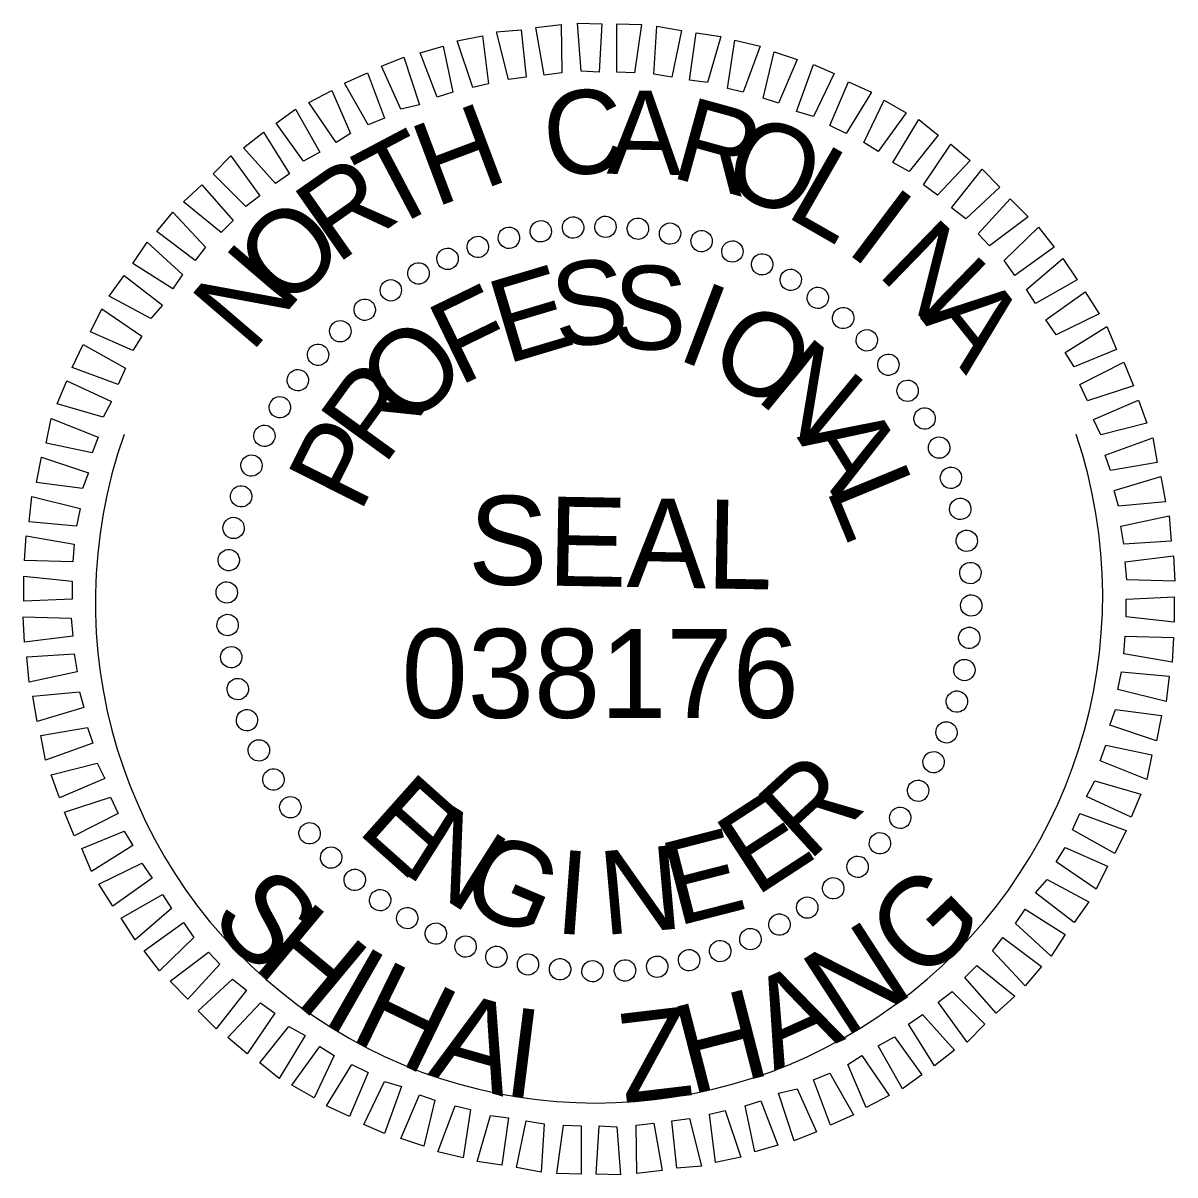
# Model space of a CAD drawing. Extents: x 885343.6 to 885383.5, y 651350.8 to 651372.8.
# Drawn here: x 885378.006 to 885379.558, y 651369.841 to 651371.393 of the extents above; entities that cross this region are included whole.
import ezdxf

# ---------------------------------------------------------------- set-up
doc = ezdxf.new("R2010")
doc.units = 0
doc.layers.add('Sheet PE Seal Cell', color=7, linetype='Continuous')
doc.layers.add('Sheet Plot Border Outside CELL', color=7, linetype='Continuous')

msp = doc.modelspace()

# ---------------------------------------------------------------- linework, layer by layer
at = {"layer": 'Sheet PE Seal Cell'}
for p, q in [((885378.7041, 651371.1119), (885378.7041, 651371.1119)), ((885378.7471, 651371.1179), (885378.7471, 651371.1179)), ((885378.7911, 651371.1189), (885378.7911, 651371.1189)), ((885378.8351, 651371.1159), (885378.8351, 651371.1159)), ((885378.6601, 651371.1039), (885378.6601, 651371.1039)), ((885378.8781, 651371.1089), (885378.8781, 651371.1089)), ((885378.9201, 651371.0999), (885378.9201, 651371.0999)), ((885378.6181, 651371.0919), (885378.6181, 651371.0919)), ((885378.9621, 651371.0859), (885378.9621, 651371.0859)), ((885378.5781, 651371.0759), (885378.5781, 651371.0759)), ((885379.0021, 651371.0679), (885379.0021, 651371.0679)), ((885378.5391, 651371.0559), (885378.5391, 651371.0559)), ((885379.0411, 651371.0479), (885379.0411, 651371.0479)), ((885378.5011, 651371.0329), (885378.5011, 651371.0329)), ((885379.0771, 651371.0229), (885379.0771, 651371.0229)), ((885378.4661, 651371.0079), (885378.4661, 651371.0079)), ((885379.1121, 651370.9959), (885379.1121, 651370.9959)), ((885378.4331, 651370.9779), (885378.4331, 651370.9779)), ((885379.1431, 651370.9659), (885379.1431, 651370.9659)), ((885378.4031, 651370.9469), (885378.4031, 651370.9469)), ((885379.1731, 651370.9329), (885379.1731, 651370.9329)), ((885378.3761, 651370.9119), (885378.3761, 651370.9119)), ((885379.1981, 651370.8979), (885379.1981, 651370.8979)), ((885378.3511, 651370.8759), (885378.3511, 651370.8759)), ((885379.2211, 651370.8599), (885379.2211, 651370.8599)), ((885378.3311, 651370.8369), (885378.3311, 651370.8369)), ((885379.2411, 651370.8209), (885379.2411, 651370.8209)), ((885378.3131, 651370.7969), (885378.3131, 651370.7969)), ((885379.2571, 651370.7809), (885379.2571, 651370.7809)), ((885378.2991, 651370.7549), (885378.2991, 651370.7549)), ((885379.2691, 651370.7389), (885379.2691, 651370.7389)), ((885378.2901, 651370.7129), (885378.2901, 651370.7129)), ((885379.2771, 651370.6949), (885379.2771, 651370.6949)), ((885378.2831, 651370.6699), (885378.2831, 651370.6699)), ((885379.2831, 651370.6519), (885379.2831, 651370.6519)), ((885378.2801, 651370.6259), (885378.2801, 651370.6259)), ((885379.2841, 651370.6079), (885379.2841, 651370.6079)), ((885378.2811, 651370.5819), (885378.2811, 651370.5819)), ((885379.2811, 651370.5639), (885379.2811, 651370.5639)), ((885378.2871, 651370.5389), (885378.2871, 651370.5389)), ((885379.2741, 651370.5209), (885379.2741, 651370.5209)), ((885378.2951, 651370.4949), (885378.2951, 651370.4949)), ((885379.2651, 651370.4789), (885379.2651, 651370.4789)), ((885378.3071, 651370.4529), (885378.3071, 651370.4529)), ((885379.2511, 651370.4369), (885379.2511, 651370.4369)), ((885378.3231, 651370.4129), (885378.3231, 651370.4129)), ((885379.2331, 651370.3969), (885379.2331, 651370.3969)), ((885378.3431, 651370.3739), (885378.3431, 651370.3739)), ((885379.2131, 651370.3579), (885379.2131, 651370.3579)), ((885378.3661, 651370.3359), (885378.3661, 651370.3359)), ((885379.1881, 651370.3219), (885379.1881, 651370.3219)), ((885378.3911, 651370.3009), (885378.3911, 651370.3009)), ((885379.1611, 651370.2869), (885379.1611, 651370.2869)), ((885378.4211, 651370.2679), (885378.4211, 651370.2679)), ((885379.1311, 651370.2559), (885379.1311, 651370.2559)), ((885378.4521, 651370.2379), (885378.4521, 651370.2379)), ((885379.0981, 651370.2259), (885379.0981, 651370.2259)), ((885378.4871, 651370.2109), (885378.4871, 651370.2109)), ((885379.0631, 651370.2009), (885379.0631, 651370.2009)), ((885378.5231, 651370.1859), (885378.5231, 651370.1859)), ((885379.0251, 651370.1779), (885379.0251, 651370.1779)), ((885378.5621, 651370.1659), (885378.5621, 651370.1659)), ((885378.6021, 651370.1479), (885378.6021, 651370.1479)), ((885378.9861, 651370.1579), (885378.9861, 651370.1579)), ((885378.6441, 651370.1339), (885378.6441, 651370.1339)), ((885378.9461, 651370.1419), (885378.9461, 651370.1419)), ((885378.6861, 651370.1249), (885378.6861, 651370.1249)), ((885378.7291, 651370.1179), (885378.7291, 651370.1179)), ((885378.8171, 651370.1159), (885378.8171, 651370.1159)), ((885378.8601, 651370.1219), (885378.8601, 651370.1219)), ((885378.9041, 651370.1299), (885378.9041, 651370.1299)), ((885378.7731, 651370.1149), (885378.7731, 651370.1149))]:
    msp.add_line(p, q, dxfattribs=at)
for points in [[(885378.7081, 651371.3229), (885378.6971, 651371.3869), (885378.7311, 651371.3909), (885378.7321, 651371.3259)], [(885378.7581, 651371.3279), (885378.7531, 651371.3929), (885378.7861, 651371.3919), (885378.7821, 651371.3269)], [(885378.8061, 651371.3269), (885378.8061, 651371.3919), (885378.8391, 651371.3909), (885378.8301, 651371.3259)], [(885378.8561, 651371.3239), (885378.8601, 651371.3889), (885378.8931, 651371.3829), (885378.8801, 651371.3199)], [(885378.6121, 651371.3059), (885378.5911, 651371.3689), (885378.6251, 651371.3759), (885378.6331, 651371.3109)], [(885378.6601, 651371.3169), (885378.6441, 651371.3809), (885378.6771, 651371.3839), (885378.6841, 651371.3199)], [(885378.9041, 651371.3159), (885378.9131, 651371.3799), (885378.9461, 651371.3749), (885378.9281, 651371.3129)], [(885378.5641, 651371.2929), (885378.5411, 651371.3529), (885378.5721, 651371.3619), (885378.5851, 651371.2999)], [(885378.9551, 651371.3049), (885378.9651, 651371.3699), (885378.9991, 651371.3619), (885378.9761, 651371.2999)], [(885378.5151, 651371.2769), (885378.4891, 651371.3349), (885378.5191, 651371.3469), (885378.5401, 651371.2829)], [(885379.0031, 651371.2919), (885379.0181, 651371.3539), (885379.0491, 651371.3439), (885379.0241, 651371.2849)], [(885379.0481, 651371.2739), (885379.0711, 651371.3369), (885379.0991, 651371.3249), (885379.0711, 651371.2669)], [(885378.4711, 651371.2559), (885378.4391, 651371.3119), (885378.4701, 651371.3259), (885378.4931, 651371.2649)], [(885379.0931, 651371.2549), (885379.1181, 651371.3139), (885379.1491, 651371.2999), (885379.1151, 651371.2439)], [(885378.4281, 651371.2319), (885378.3911, 651371.2859), (885378.4221, 651371.3019), (885378.4471, 651371.2439)], [(885379.1391, 651371.2319), (885379.1661, 651371.2889), (885379.1961, 651371.2719), (885379.1581, 651371.2199)], [(885378.3841, 651371.2069), (885378.3471, 651371.2579), (885378.3731, 651371.2769), (885378.4061, 651371.2189)], [(885379.1781, 651371.2049), (885379.2131, 651371.2629), (885379.2391, 651371.2419), (885379.2001, 651371.1929)], [(885378.3461, 651371.1769), (885378.3031, 651371.2249), (885378.3301, 651371.2459), (885378.3651, 651371.1899)], [(885379.2191, 651371.1749), (885379.2561, 651371.2299), (885379.2821, 651371.2079), (885379.2381, 651371.1609)], [(885378.3061, 651371.1459), (885378.2621, 651371.1899), (885378.2861, 651371.2139), (885378.3251, 651371.1599)], [(885379.2571, 651371.1439), (885379.2981, 651371.1959), (885379.3221, 651371.1719), (885379.2761, 651371.1289)], [(885378.2731, 651371.1109), (885378.2221, 651371.1519), (885378.2471, 651371.1749), (885378.2891, 651371.1269)], [(885379.2931, 651371.1089), (885379.3361, 651371.1559), (885379.3601, 651371.1319), (885379.3081, 651371.0929)], [(885378.2381, 651371.0729), (885378.1861, 651371.1119), (885378.2081, 651371.1379), (885378.2521, 651371.0909)], [(885379.3281, 651371.0729), (885379.3741, 651371.1179), (885379.3951, 651371.0909), (885379.3421, 651371.0529)], [(885378.2081, 651371.0349), (885378.1541, 651371.0689), (885378.1731, 651371.0979), (885378.2211, 651371.0539)], [(885379.3581, 651371.0339), (885379.4071, 651371.0759), (885379.4261, 651371.0469), (885379.3701, 651371.0149)], [(885378.1781, 651370.9949), (885378.1221, 651371.0249), (885378.1421, 651371.0529), (885378.1941, 651371.0129)], [(885379.3841, 651370.9929), (885379.4371, 651371.0309), (885379.4561, 651371.0009), (885379.3981, 651370.9729)], [(885378.1541, 651370.9519), (885378.0971, 651370.9769), (885378.1121, 651371.0079), (885378.1661, 651370.9709)], [(885379.4101, 651370.9489), (885379.4661, 651370.9839), (885379.4791, 651370.9529), (885379.4221, 651370.9299)], [(885378.1341, 651370.9059), (885378.0721, 651370.9289), (885378.0871, 651370.9599), (885378.1441, 651370.9279)], [(885379.4301, 651370.9059), (885379.4891, 651370.9359), (885379.5021, 651370.9039), (885379.4401, 651370.8839)], [(885378.1141, 651370.8619), (885378.0521, 651370.8799), (885378.0651, 651370.9109), (885378.1251, 651370.8829)], [(885379.4481, 651370.8589), (885379.5091, 651370.8849), (885379.5201, 651370.8539), (885379.4581, 651370.8379)], [(885378.0991, 651370.8139), (885378.0371, 651370.8269), (885378.0441, 651370.8599), (885378.1071, 651370.8349)], [(885379.4641, 651370.8109), (885379.5281, 651370.8339), (885379.5341, 651370.8009), (885379.4711, 651370.7899)], [(885378.0861, 651370.7659), (885378.0241, 651370.7739), (885378.0311, 651370.8079), (885378.0941, 651370.7869)], [(885379.4761, 651370.7629), (885379.5391, 651370.7819), (885379.5451, 651370.7479), (885379.4821, 651370.7419)], [(885378.0781, 651370.7149), (885378.0141, 651370.7209), (885378.0181, 651370.7549), (885378.0831, 651370.7389)], [(885379.4851, 651370.7149), (885379.5501, 651370.7289), (885379.5531, 651370.6949), (885379.4891, 651370.6909)], [(885378.0731, 651370.6669), (885378.0081, 651370.6689), (885378.0101, 651370.7019), (885378.0751, 651370.6909)], [(885379.4911, 651370.6669), (885379.5561, 651370.6749), (885379.5581, 651370.6409), (885379.4931, 651370.6429)], [(885378.0721, 651370.6169), (885378.0071, 651370.6139), (885378.0071, 651370.6479), (885378.0721, 651370.6409)], [(885379.4921, 651370.6169), (885379.5571, 651370.6199), (885379.5571, 651370.5859), (885379.4921, 651370.5929)], [(885378.0731, 651370.5669), (885378.0081, 651370.5589), (885378.0061, 651370.5929), (885378.0711, 651370.5909)], [(885379.4911, 651370.5669), (885379.5561, 651370.5649), (885379.5541, 651370.5319), (885379.4891, 651370.5429)], [(885378.0791, 651370.5189), (885378.0141, 651370.5049), (885378.0111, 651370.5389), (885378.0751, 651370.5429)], [(885379.4861, 651370.5189), (885379.5501, 651370.5129), (885379.5461, 651370.4789), (885379.4811, 651370.4949)], [(885378.0881, 651370.4709), (885378.0251, 651370.4519), (885378.0191, 651370.4859), (885378.0821, 651370.4919)], [(885379.4781, 651370.4679), (885379.5401, 651370.4599), (885379.5331, 651370.4259), (885379.4701, 651370.4469)], [(885378.1001, 651370.4229), (885378.0361, 651370.3999), (885378.0301, 651370.4329), (885378.0931, 651370.4439)], [(885379.4651, 651370.4199), (885379.5271, 651370.4069), (885379.5201, 651370.3739), (885379.4571, 651370.3989)], [(885378.1161, 651370.3749), (885378.0551, 651370.3489), (885378.0441, 651370.3799), (885378.1061, 651370.3959)], [(885379.4501, 651370.3719), (885379.5121, 651370.3539), (885379.4991, 651370.3229), (885379.4391, 651370.3509)], [(885378.1341, 651370.3279), (885378.0751, 651370.2979), (885378.0621, 651370.3299), (885378.1241, 651370.3499)], [(885379.4301, 651370.3279), (885379.4921, 651370.3049), (885379.4771, 651370.2739), (885379.4201, 651370.3059)], [(885378.1541, 651370.2849), (885378.0981, 651370.2499), (885378.0851, 651370.2809), (885378.1421, 651370.3039)], [(885379.4101, 651370.2819), (885379.4671, 651370.2569), (885379.4521, 651370.2259), (885379.3981, 651370.2629)], [(885378.1801, 651370.2409), (885378.1271, 651370.2029), (885378.1081, 651370.2329), (885378.1661, 651370.2609)], [(885379.3861, 651370.2389), (885379.4421, 651370.2089), (885379.4221, 651370.1809), (885379.3701, 651370.2209)], [(885378.2061, 651370.1999), (885378.1571, 651370.1579), (885378.1381, 651370.1869), (885378.1941, 651370.2189)], [(885379.3561, 651370.1989), (885379.4101, 651370.1649), (885379.3911, 651370.1359), (885379.3431, 651370.1799)], [(885378.2361, 651370.1609), (885378.1901, 651370.1159), (885378.1691, 651370.1429), (885378.2221, 651370.1809)], [(885379.3261, 651370.1609), (885379.3781, 651370.1219), (885379.3561, 651370.0959), (885379.3121, 651370.1429)], [(885378.2711, 651370.1249), (885378.2281, 651370.0779), (885378.2041, 651370.1019), (885378.2561, 651370.1409)], [(885379.2911, 651370.1229), (885379.3421, 651370.0819), (885379.3171, 651370.0589), (885379.2751, 651370.1069)], [(885378.3071, 651370.0899), (885378.2661, 651370.0379), (885378.2421, 651370.0619), (885378.2881, 651370.1049)], [(885379.2581, 651370.0879), (885379.3021, 651370.0439), (885379.2781, 651370.0199), (885379.2391, 651370.0739)], [(885378.3451, 651370.0589), (885378.3081, 651370.0039), (885378.2821, 651370.0259), (885378.3261, 651370.0729)], [(885379.2181, 651370.0569), (885379.2611, 651370.0089), (885379.2341, 651369.9879), (885379.1991, 651370.0439)], [(885378.3861, 651370.0289), (885378.3511, 651369.9709), (885378.3251, 651369.9919), (885378.3641, 651370.0409)], [(885379.1801, 651370.0269), (885379.2171, 651369.9759), (885379.1911, 651369.9569), (885379.1581, 651370.0149)], [(885378.4251, 651370.0019), (885378.3981, 651369.9449), (885378.3681, 651369.9619), (885378.4061, 651370.0139)], [(885379.1361, 651370.0019), (885379.1731, 651369.9479), (885379.1421, 651369.9319), (885379.1171, 651369.9899)], [(885378.4711, 651369.9789), (885378.4461, 651369.9199), (885378.4151, 651369.9339), (885378.4491, 651369.9899)], [(885379.0931, 651369.9779), (885379.1251, 651369.9219), (885379.0941, 651369.9079), (885379.0711, 651369.9689)], [(885378.5161, 651369.9599), (885378.4931, 651369.8969), (885378.4651, 651369.9089), (885378.4931, 651369.9669)], [(885378.5611, 651369.9419), (885378.5461, 651369.8799), (885378.5151, 651369.8899), (885378.5401, 651369.9489)], [(885379.0491, 651369.9569), (885379.0751, 651369.8989), (885379.0451, 651369.8869), (885379.0241, 651369.9509)], [(885378.6091, 651369.9289), (885378.5991, 651369.8639), (885378.5651, 651369.8719), (885378.5881, 651369.9339)], [(885379.0001, 651369.9409), (885379.0231, 651369.8809), (885378.9921, 651369.8719), (885378.9791, 651369.9339)], [(885378.6601, 651369.9179), (885378.6511, 651369.8539), (885378.6181, 651369.8589), (885378.6361, 651369.9209)], [(885378.9041, 651369.9169), (885378.9201, 651369.8529), (885378.8871, 651369.8499), (885378.8801, 651369.9139)], [(885378.9521, 651369.9279), (885378.9731, 651369.8649), (885378.9391, 651369.8579), (885378.9311, 651369.9229)], [(885378.7081, 651369.9099), (885378.7041, 651369.8449), (885378.6711, 651369.8509), (885378.6841, 651369.9139)], [(885378.7581, 651369.9069), (885378.7581, 651369.8419), (885378.7251, 651369.8429), (885378.7341, 651369.9079)], [(885378.8061, 651369.9059), (885378.8111, 651369.8409), (885378.7781, 651369.8419), (885378.7821, 651369.9069)], [(885378.8561, 651369.9109), (885378.8671, 651369.8469), (885378.8331, 651369.8429), (885378.8321, 651369.9079)]]:
    msp.add_lwpolyline(points, close=True, dxfattribs=at)
for centre, major_axis in [((885378.7036, 651371.1123), (-0.0023, 0.0142)), ((885378.7471, 651371.1173), (-0.001, 0.0144)), ((885378.7908, 651371.1184), (0.0003, 0.0144)), ((885378.8345, 651371.1158), (0.0015, 0.0143)), ((885378.8778, 651371.1093), (0.0027, 0.0141)), ((885378.6607, 651371.1036), (-0.0035, 0.014)), ((885378.9203, 651371.0991), (0.004, 0.0138)), ((885378.6188, 651371.0912), (-0.0047, 0.0136)), ((885378.9618, 651371.0852), (0.0052, 0.0134)), ((885378.578, 651371.0752), (-0.0059, 0.0132)), ((885379.0019, 651371.0678), (0.0063, 0.0129)), ((885378.5389, 651371.0556), (-0.007, 0.0126)), ((885379.0404, 651371.0469), (0.0074, 0.0123)), ((885378.5016, 651371.0328), (-0.0081, 0.0119)), ((885379.0769, 651371.0227), (0.0085, 0.0116)), ((885378.4664, 651371.0067), (-0.0091, 0.0112)), ((885379.1111, 651370.9955), (0.0094, 0.0109)), ((885378.4336, 651370.9777), (-0.01, 0.0104)), ((885379.1429, 651370.9654), (0.0104, 0.01)), ((885378.4035, 651370.946), (-0.0109, 0.0094)), ((885379.1719, 651370.9326), (0.0112, 0.0091)), ((885378.3763, 651370.9117), (-0.0116, 0.0085)), ((885379.1979, 651370.8974), (0.0119, 0.0081)), ((885378.3521, 651370.8753), (-0.0123, 0.0074)), ((885379.2208, 651370.8601), (0.0126, 0.007)), ((885378.3312, 651370.8368), (-0.0129, 0.0063)), ((885379.2403, 651370.8209), (0.0132, 0.0059)), ((885378.3138, 651370.7967), (-0.0134, 0.0052)), ((885379.2563, 651370.7802), (0.0136, 0.0047)), ((885378.2999, 651370.7552), (-0.0138, 0.004)), ((885379.2688, 651370.7383), (0.014, 0.0035)), ((885378.2897, 651370.7126), (-0.0141, 0.0027)), ((885379.2775, 651370.6954), (0.0142, 0.0023)), ((885378.2832, 651370.6693), (-0.0143, 0.0015)), ((885379.2824, 651370.6519), (0.0144, 0.001)), ((885378.2805, 651370.6257), (-0.0144, 0.0003)), ((885379.2836, 651370.6082), (0.0144, -0.0003)), ((885378.2817, 651370.5819), (-0.0144, -0.001)), ((885379.2809, 651370.5645), (0.0143, -0.0015)), ((885378.2866, 651370.5384), (-0.0142, -0.0023)), ((885379.2744, 651370.5212), (0.0141, -0.0027)), ((885378.2954, 651370.4956), (-0.014, -0.0035)), ((885379.2642, 651370.4787), (0.0138, -0.004)), ((885378.3078, 651370.4536), (-0.0136, -0.0047)), ((885379.2503, 651370.4372), (0.0134, -0.0052)), ((885378.3238, 651370.4129), (-0.0132, -0.0059)), ((885379.2329, 651370.397), (0.0129, -0.0063)), ((885378.3434, 651370.3737), (-0.0126, -0.007)), ((885379.212, 651370.3586), (0.0123, -0.0074)), ((885378.3662, 651370.3364), (-0.0119, -0.0081)), ((885379.1879, 651370.3221), (0.0116, -0.0085)), ((885378.3922, 651370.3012), (-0.0112, -0.0091)), ((885379.1606, 651370.2878), (0.0109, -0.0094)), ((885378.4212, 651370.2685), (-0.0104, -0.01)), ((885379.1305, 651370.2561), (0.01, -0.0104)), ((885378.453, 651370.2384), (-0.0094, -0.0109)), ((885379.0977, 651370.2271), (0.0091, -0.0112)), ((885378.4872, 651370.2111), (-0.0085, -0.0116)), ((885379.0626, 651370.2011), (0.0081, -0.0119)), ((885378.5237, 651370.187), (-0.0074, -0.0123)), ((885379.0252, 651370.1782), (0.007, -0.0126)), ((885378.5622, 651370.1661), (-0.0063, -0.0129)), ((885378.6023, 651370.1486), (-0.0052, -0.0134)), ((885378.9861, 651370.1587), (0.0059, -0.0132)), ((885378.6438, 651370.1347), (-0.004, -0.0138)), ((885378.9454, 651370.1426), (0.0047, -0.0136)), ((885378.6864, 651370.1245), (-0.0027, -0.0141)), ((885378.7296, 651370.1181), (-0.0015, -0.0143)), ((885378.8171, 651370.1165), (0.001, -0.0144)), ((885378.8605, 651370.1215), (0.0023, -0.0142)), ((885378.9034, 651370.1302), (0.0035, -0.014)), ((885378.7733, 651370.1154), (-0.0003, -0.0144))]:
    msp.add_ellipse(centre, major_axis=major_axis, ratio=0.999708, dxfattribs=at)
at = {"layer": 'Sheet Plot Border Outside CELL'}
msp.add_ellipse((885378.7821, 651370.6169), major_axis=(0.4509, 0.5104), ratio=0.993455, start_param=1.958957, end_param=5.764947, dxfattribs=at)

# ---------------------------------------------------------------- texts
at = {"layer": 'Sheet PE Seal Cell'}
for s, height, rotation, p in [('C', 0.1128, 6.2199, (885378.7131, 651371.1839)), ('A', 0.1128, 359.0203, (885378.7921, 651371.1899)), ('H', 0.1128, 20.6195, (885378.5611, 651371.1439)), ('R', 0.1128, 344.6211, (885378.8761, 651371.1859)), ('T', 0.1128, 27.8198, (885378.4961, 651371.1109)), ('O', 0.1128, 337.4212, (885378.9431, 651371.1709)), ('L', 0.1128, 330.2209, (885379.0311, 651371.1339)), ('R', 0.1128, 35.0205, (885378.4281, 651371.0669)), ('I', 0.1128, 323.0201, (885379.1121, 651371.0859)), ('O', 0.1128, 42.2217, (885378.3591, 651371.0049)), ('N', 0.1128, 315.8189, (885379.1551, 651371.0549)), ('N', 0.1128, 49.4235, (885378.3131, 651370.9469)), ('E', 0.1128, 16.6111, (885378.6571, 651370.9329)), ('S', 0.1128, 7.2556, (885378.7261, 651370.9539)), ('S', 0.1128, 357.9004, (885378.7981, 651370.9549)), ('F', 0.1128, 25.967, (885378.5931, 651370.9029)), ('I', 0.1128, 339.1896, (885378.8841, 651370.9409)), ('A', 0.1128, 308.6172, (885379.2141, 651370.9959)), ('O', 0.1128, 329.8335, (885378.9241, 651370.9269)), ('O', 0.1128, 44.6812, (885378.5271, 651370.8439)), ('N', 0.1128, 320.4766, (885378.9911, 651370.8869)), ('R', 0.1128, 54.0397, (885378.4921, 651370.7949)), ('P', 0.1128, 63.3989, (885378.4601, 651370.7309)), ('A', 0.1128, 301.7603, (885379.0481, 651370.8349)), ('L', 0.1128, 292.4008, (885379.0871, 651370.7659)), ('SEAL', 0.11996, 359, (885378.6051, 651370.6369)), ('R', 0.1128, 42.4814, (885379.0641, 651370.2619)), ('E', 0.1128, 318.2769, (885378.4541, 651370.3039)), ('E', 0.1128, 33.1241, (885378.9931, 651370.2149)), ('N', 0.1128, 327.634, (885378.5141, 651370.2499)), ('E', 0.1128, 14.4118, (885378.8871, 651370.1759)), ('G', 0.1128, 336.9902, (885378.5901, 651370.2049)), ('I', 0.1128, 355.7012, (885378.7211, 651370.1669)), ('N', 0.1128, 5.0564, (885378.7881, 651370.1639)), ('S', 0.12, 312.8717, (885378.2543, 651370.1845)), ('G', 0.12, 43.5199, (885379.2162, 651370.0961)), ('H', 0.12, 320.2176, (885378.313, 651370.1213)), ('N', 0.12, 32.9666, (885379.1123, 651370.0243)), ('I', 0.12, 330.2264, (885378.405, 651370.0482)), ('H', 0.12, 334.0349, (885378.4432, 651370.0248)), ('A', 0.12, 24.2541, (885379.018, 651369.9803)), ('H', 0.12, 14.3908, (885378.9048, 651369.9485)), ('A', 0.12, 344.0225, (885378.5501, 651369.9758)), ('I', 0.12, 352.8443, (885378.6505, 651369.9485)), ('Z', 0.12, 6.7663, (885378.8148, 651369.9375))]:
    msp.add_text(s, height=height, rotation=rotation, dxfattribs=at).set_placement(p)
msp.add_text('038176 ', height=0.11996, dxfattribs=at).set_placement((885378.516, 651370.4567))

doc.saveas('drawing.dxf')
